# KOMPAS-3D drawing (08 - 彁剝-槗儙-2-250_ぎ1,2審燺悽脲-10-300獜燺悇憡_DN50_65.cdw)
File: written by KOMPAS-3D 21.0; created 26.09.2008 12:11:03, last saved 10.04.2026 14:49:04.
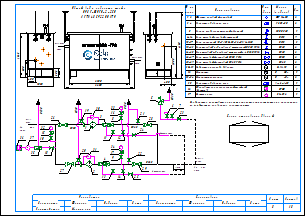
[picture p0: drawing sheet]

Sheets 1-2: A3, landscape

Document properties: Наименование: Макро:21; Автор: RaskoAdmin; Форматы листов документа: 2xA3; Полное имя файла: \\UR38nt01\Departments\КТО\КБ ПУРДГ\Заявки\Прайс-лист на типовые шкафы ГРПШ\ПРДГ_стандарт_20_03_2026\ПРДГ с РДСК\ПРДГ-ШУГО-2-250_до1,2МПа_Рвых-10-300кПа_РДСК_DN50_65.cdw

Title block, sheet 1: Наименование: Пункт учета газа / ПУГ-Ш-400-Р / ЛГТИ.485922.001ТУ; designation: ЛГТИ.03.4411141; sheet number: 1; Количество листов документа: 2; organisation: ООО "ЭЛЬСТЕР Газэлектроника"; Форматы листов документа: A3; stored path: C:\Рабочие документы\Компас\ПУГ\Схема.cdw; Разработал: Устинов; Проверил: Кошкин; Утвердил: Кошкин
Title block, sheet 2: sheet number: 2; stored path: D:\Рабочие документы\Заявки\ПУРДГ\ПУРДГ-ШУЭО-2-100-Р 4411220.cdw; designation, second copy: ЛГТИ.03.4411141-

Views: Вид 1, Вид 2
Referenced files: wcvoit.frw
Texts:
  Normal
  Вход
  газа
  PDI
  Выход
  Р=     кПа
  DN65
  DN50
  DN20
  Импульс DN20
  ≥5DN
  HYSWLongFangSong
  № на
  схеме
  Усл.
  обозн.
  Марка
  (модель)
  Кол.
  Фильтр газовый фланцевый
  ФГ 16-50
  Регулятор давления газа
  РДCК-50
  Клапан предохранительный сбросной
  КПС DN20
  Кран шаровой газовый латунный
  DN15
  Кран кнопочный VE-РАСКО-НЗ-1,6-G1/2-М20
  Кран шаровой "под приварку" штуцерный DN20 PN16
  Кран шаровой "под приварку" штуцерный п/п DN20 PN16
  Кран шаровой фланцевый DN50 PN16
  Кран шаровой фланцевый DN65 PN16
  Индикатор перепада давления
  Delta 15
  Манометр
  Манометр-напоромер
  0...     МПа
  0...     кПа
  Обогреватель газогорелочный шкафной
  (Эльтон")
  Счетчик газа
  Venio-A-15
  ОГШН
  BK-G1,6
  Общий вид и габариты шкафа
  ПРДГ-ШУГО-2-250
  Выход газа
  Вход газа
  Схема открывания дверей
  Р=        МПа
  logo-rasko-ge.png
  Предприятие изготовитель может заменять комплектующие на аналогичные,
  не ухудшающие заявленных характеристик.
  Должность
  Конструктор
  Фамилия
  Подпись
  Дата
  Согласовано
  Максимкин
  Лист
  Листов
  POLYLINE_STYLE_0.18_RGB_0_0_0
  POLYLINE_STYLE_0.50_RGB_0_0_0
  POLYLINE_STYLE_0.34_RGB_0_0_0
  PHANTOM_RGB_0_0_0_SC_1_THICK_0.18
  K5LT_THIN_RGB_0_0_0_THICK_0.18
  K5LT32769_RGB_0_0_0_THICK_0.18
  K5LT12_RGB_0_0_0_SC_1_THICK_0.18
  K5LT_DASHED_RGB_0_0_0_SC_1_THICK_0.18
  ACISOTGL_RGB_0_0_0_SC_0.8_THICK_0.25
  CONTINUOUS_RGB_0_127_31_THICK_0.3
  CONTINUOUS_RGB_0_0_255_THICK_0.35
  CONTINUOUS_RGB_255_0_0_THICK_0.35
  POLYLINE_STYLE_0.25_RGB_0_0_0
  CONTINUOUS_RGB_0_0_0_THICK_0.5
  POLYLINE_STYLE_0.35_RGB_0_0_255
  CONTINUOUS_RGB_0_0_0_THICK_0.4
  CONTINUOUS_RGB_0_0_0_THICK_0.35
  Без оформления
Dimensions and other numbers on the sheet: 1; 2; 3; 4; 5; 10; 27; 28; 29; 23; 8; 12; 18; 19; 20; 21; 22; 25; 24; 30; 31; 15; 16; 35; 36; 26; 6; 7; 11; 14; 13; 33; 1, 2; 3, 4; 6-14; 9; 15-17; 18-23; 24-25; 26-27; 28-29; 30-31; 32; 33-34; 37; 400; 1050; 500; 305; 2300; 1565; 2600; 17; 34; 1000; 4130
